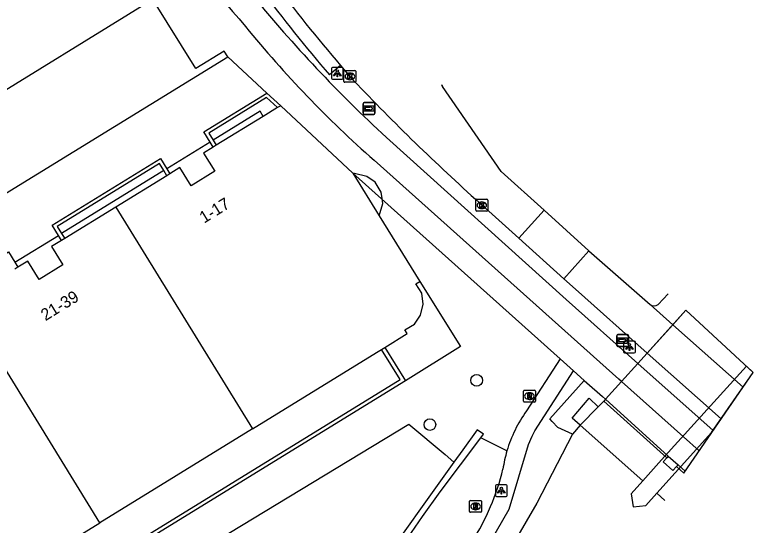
# Model space of a CAD drawing. Extents: x 160664 to 161506, y 382245 to 383288.
# Drawn here: x 161443.8 to 161505.9, y 382791.2 to 382834.1 of the extents above; entities that cross this region are included whole.
import ezdxf

# ---------------------------------------------------------------- set-up
doc = ezdxf.new("R2010")
doc.units = 0
for name, color, linetype in [('IMGEO_Berm_open', 7, 'Continuous'), ('IMGEO_Boom', 7, 'Continuous'), ('IMGEO_Dek', 7, 'Continuous'), ('IMGEO_Fietspad_gesloten', 7, 'Continuous'), ('IMGEO_Grasland_overig', 7, 'Continuous'), ('IMGEO_Groenvoorziening', 7, 'Continuous'), ('IMGEO_Haag', 7, 'Continuous'), ('IMGEO_Kolk', 7, 'Continuous'), ('IMGEO_Lichtpunt', 7, 'Continuous'), ('IMGEO_Muur', 7, 'Continuous'), ('IMGEO_Pand', 7, 'Continuous'), ('IMGEO_Pand_nummerreeks', 7, 'Continuous'), ('IMGEO_Pand_overbouw', 7, 'Continuous'), ('IMGEO_Pijler', 7, 'Continuous'), ('IMGEO_Rijbaan_lokaal_gesloten', 7, 'Continuous'), ('IMGEO_Rijbaan_lokaal_open', 7, 'Continuous'), ('IMGEO_Rioolput', 7, 'Continuous'), ('IMGEO_Stuw', 7, 'Continuous'), ('IMGEO_Verkeerseiland_gesloten', 7, 'Continuous'), ('IMGEO_Voetpad_halfverhard', 7, 'Continuous'), ('IMGEO_Voetpad_open', 7, 'Continuous'), ('IMGEO_Waterloop', 7, 'Continuous'), ('IMGEO_Wegwijzer', 7, 'Continuous')]:
    doc.layers.add(name, color=color, linetype=linetype)

msp = doc.modelspace()

# ---------------------------------------------------------------- linework, layer by layer
at = {"layer": 'IMGEO_Berm_open'}
msp.add_lwpolyline([(161471.165, 382829.87), (161470.251, 382829.074)], dxfattribs=at)
msp.add_arc((161556.487, 382903.934), 114.196, 211.69587, 220.96043, dxfattribs=at)
at = {"layer": 'IMGEO_Boom'}
for centre in [(161482.615, 382803.394), (161478.686, 382799.671)]:
    msp.add_circle(centre, 0.489, dxfattribs=at)
at = {"layer": 'IMGEO_Dek'}
msp.add_lwpolyline([(161500.029, 382795.601), (161505.863, 382804.066), (161500.209, 382809.288), (161500.209, 382809.288), (161496.961, 382805.691), (161496.176, 382804.823), (161494.795, 382803.293), (161493.457, 382801.811), (161493.311, 382801.649), (161498.591, 382796.889), (161498.306, 382796.552), (161499.095, 382795.805), (161499.425, 382796.144), (161500.029, 382795.601)], close=True, dxfattribs=at)
at = {"layer": 'IMGEO_Fietspad_gesloten'}
for points in [[(161496.176, 382804.823), (161490.146, 382810.192), (161475.03, 382823.813)], [(161494.795, 382803.293), (161494.557, 382803.506), (161473.997, 382821.895)], [(161496.176, 382804.823), (161494.795, 382803.293)], [(161502.503, 382799.191), (161496.176, 382804.823)], [(161494.795, 382803.293), (161500, 382798.638), (161501.313, 382797.464)]]:
    msp.add_lwpolyline(points, dxfattribs=at)
for centre, radius, start, end in [((161526.304, 382887.974), 83.61, 211.81634, 220.98361), ((161552.726, 382908.236), 114.734, 219.12759, 227.37602), ((161535.422, 382891.768), 93.034, 219.06402, 228.68123)]:
    msp.add_arc(centre, radius, start, end, dxfattribs=at)
at = {"layer": 'IMGEO_Grasland_overig'}
for points in [[(161464.666, 382825.575), (161464.407, 382826.011), (161460.467, 382823.586)], [(161456.306, 382821.025), (161447.73, 382815.747)], [(161477.844, 382811.705), (161481.27, 382806.236), (161476.636, 382803.355)]]:
    msp.add_lwpolyline(points, dxfattribs=at)
at = {"layer": 'IMGEO_Groenvoorziening'}
for points in [[(161406.189, 382756.415), (161409.162, 382758.244), (161452.771, 382785.073), (161476.902, 382799.706), (161479.967, 382797.156), (161480.692, 382796.508)], [(161485.158, 382797.459), (161482.963, 382798.573)]]:
    msp.add_lwpolyline(points, dxfattribs=at)
at = {"layer": 'IMGEO_Haag'}
for points in [[(161482.963, 382798.573), (161483.179, 382798.86), (161482.663, 382799.23), (161481.44, 382797.556), (161480.692, 382796.508)], [(161467.968, 382776.003), (161471.38, 382781.605), (161474.698, 382786.947), (161476.209, 382789.251), (161478.06, 382791.955), (161479.541, 382794.031), (161482.963, 382798.573)], [(161480.692, 382796.508), (161474.068, 382787.223), (161467.436, 382776.857), (161466.728, 382776.728), (161465.376, 382775.633), (161460.612, 382770.74), (161461.165, 382770.238)]]:
    msp.add_lwpolyline(points, dxfattribs=at)
at = {"layer": 'IMGEO_Kolk'}
for p, q in [((161471.461, 382828.522), (161471.461, 382829.374)), ((161471.536, 382829.448), (161472.388, 382829.448)), ((161471.949, 382829.228), (161471.974, 382829.228)), ((161472.462, 382829.374), (161472.462, 382828.522)), ((161472.388, 382828.448), (161471.536, 382828.448)), ((161471.972, 382828.668), (161471.947, 382828.668)), ((161482.549, 382817.687), (161482.549, 382818.539)), ((161482.624, 382818.613), (161483.476, 382818.613)), ((161483.55, 382818.539), (161483.55, 382817.687)), ((161483.06, 382817.833), (161483.035, 382817.833)), ((161483.037, 382818.393), (161483.062, 382818.393)), ((161483.476, 382817.613), (161482.624, 382817.613))]:
    msp.add_line(p, q, dxfattribs=at)
for points in [[(161471.461, 382828.522), (161471.461, 382829.374)], [(161471.536, 382829.448), (161472.388, 382829.448)], [(161471.782, 382829.148), (161471.905, 382829.148), (161471.905, 382828.997), (161472.035, 382829.148), (161472.199, 382829.148), (161472.053, 382828.997), (161472.206, 382828.748), (161472.054, 382828.748), (161471.969, 382828.912), (161471.905, 382828.845), (161471.905, 382828.748), (161471.782, 382828.748), (161471.782, 382829.148)], [(161472.462, 382829.374), (161472.462, 382828.522)], [(161472.388, 382828.448), (161471.536, 382828.448)], [(161482.549, 382817.687), (161482.549, 382818.539)], [(161482.624, 382818.613), (161483.476, 382818.613)], [(161483.55, 382818.539), (161483.55, 382817.687)], [(161482.87, 382818.313), (161482.993, 382818.313), (161482.993, 382818.162), (161483.123, 382818.313), (161483.287, 382818.313), (161483.141, 382818.162), (161483.294, 382817.913), (161483.142, 382817.913), (161483.057, 382818.077), (161482.993, 382818.01), (161482.993, 382817.913), (161482.87, 382817.913), (161482.87, 382818.313)], [(161483.476, 382817.613), (161482.624, 382817.613)]]:
    msp.add_lwpolyline(points, dxfattribs=at)
for centre, start, end in [((161471.538, 382829.372), 91.55205, 178.44795), ((161471.538, 382829.372), 91.55205, 178.44795), ((161472.386, 382829.372), 1.55205, 88.44795), ((161472.386, 382829.372), 1.55205, 88.44795), ((161471.538, 382828.524), 181.55205, 268.44795), ((161471.538, 382828.524), 181.55205, 268.44795), ((161472.386, 382828.524), 271.55205, 358.44795), ((161472.386, 382828.524), 271.55205, 358.44795), ((161482.626, 382818.537), 91.55205, 178.44795), ((161482.626, 382818.537), 91.55205, 178.44795), ((161483.474, 382818.537), 1.55205, 88.44795), ((161483.474, 382818.537), 1.55205, 88.44795), ((161482.626, 382817.689), 181.55205, 268.44795), ((161482.626, 382817.689), 181.55205, 268.44795), ((161483.474, 382817.689), 271.55205, 358.44795), ((161483.474, 382817.689), 271.55205, 358.44795)]:
    msp.add_arc(centre, 0.0765, start, end, dxfattribs=at)
for centre, major_axis, ratio, start_param, end_param in [((161471.948, 382828.948), (-0.387, 0.002), 0.722429, 4.712389, 7.853982), ((161471.973, 382828.948), (-0.39, 0.002), 0.717154, 1.570796, 4.712389), ((161483.036, 382818.113), (-0.387, 0.002), 0.722429, 4.712389, 7.853982), ((161483.061, 382818.113), (-0.39, 0.002), 0.717154, 1.570796, 4.712389)]:
    msp.add_ellipse(centre, major_axis=major_axis, ratio=ratio, start_param=start_param, end_param=end_param, dxfattribs=at)
at = {"layer": 'IMGEO_Lichtpunt'}
for p, q in [((161470.404, 382829.606), (161470.404, 382828.799)), ((161470.404, 382829.606), (161470.404, 382828.799)), ((161471.306, 382829.701), (161470.498, 382829.701)), ((161471.306, 382829.701), (161470.498, 382829.701)), ((161471.4, 382828.799), (161471.4, 382829.606)), ((161471.4, 382828.799), (161471.4, 382829.606)), ((161470.498, 382828.705), (161471.306, 382828.705)), ((161470.498, 382828.705), (161471.306, 382828.705)), ((161495.86, 382806.7), (161495.052, 382806.7)), ((161495.86, 382806.7), (161495.052, 382806.7)), ((161494.958, 382806.605), (161494.958, 382805.798)), ((161494.958, 382806.605), (161494.958, 382805.798)), ((161495.954, 382805.798), (161495.954, 382806.605)), ((161495.954, 382805.798), (161495.954, 382806.605)), ((161495.052, 382805.704), (161495.86, 382805.704)), ((161495.052, 382805.704), (161495.86, 382805.704)), ((161484.191, 382794.525), (161484.191, 382793.718)), ((161484.191, 382794.525), (161484.191, 382793.718)), ((161485.093, 382794.62), (161484.285, 382794.62)), ((161485.093, 382794.62), (161484.285, 382794.62)), ((161485.187, 382793.718), (161485.187, 382794.525)), ((161485.187, 382793.718), (161485.187, 382794.525)), ((161484.285, 382793.624), (161485.093, 382793.624)), ((161484.285, 382793.624), (161485.093, 382793.624))]:
    msp.add_line(p, q, dxfattribs=at)
for points in [[(161470.778, 382829.27), (161470.817, 382829.242), (161470.629, 382828.98), (161470.591, 382829.007), (161470.778, 382829.27)], [(161470.88, 382829.222), (161470.927, 382829.222), (161470.927, 382828.9), (161470.88, 382828.9), (161470.88, 382829.222)], [(161470.99, 382829.242), (161471.028, 382829.269), (161471.215, 382829.007), (161471.176, 382828.979), (161470.99, 382829.242)], [(161495.332, 382806.269), (161495.371, 382806.241), (161495.183, 382805.979), (161495.145, 382806.006), (161495.332, 382806.269)], [(161495.434, 382806.221), (161495.481, 382806.221), (161495.481, 382805.899), (161495.434, 382805.899), (161495.434, 382806.221)], [(161495.544, 382806.241), (161495.582, 382806.268), (161495.769, 382806.006), (161495.73, 382805.978), (161495.544, 382806.241)], [(161484.565, 382794.189), (161484.604, 382794.161), (161484.416, 382793.899), (161484.378, 382793.926), (161484.565, 382794.189)], [(161484.667, 382794.141), (161484.714, 382794.141), (161484.714, 382793.819), (161484.667, 382793.819), (161484.667, 382794.141)], [(161484.777, 382794.161), (161484.815, 382794.188), (161485.002, 382793.926), (161484.963, 382793.898), (161484.777, 382794.161)]]:
    msp.add_lwpolyline(points, dxfattribs=at)
for centre in [(161470.903, 382829.404), (161495.457, 382806.403), (161484.69, 382794.323)]:
    msp.add_circle(centre, 0.0994, dxfattribs=at)
for centre, start, end in [((161470.498, 382829.606), 90, 180), ((161470.498, 382829.606), 90, 180), ((161471.306, 382829.606), 0, 90), ((161471.306, 382829.606), 0, 90), ((161470.498, 382828.799), 180, 270), ((161470.498, 382828.799), 180, 270), ((161471.306, 382828.799), 270, 0), ((161471.306, 382828.799), 270, 360), ((161495.052, 382806.605), 90, 180), ((161495.052, 382806.605), 90, 180), ((161495.86, 382806.605), 0, 90), ((161495.86, 382806.605), 0, 90), ((161495.052, 382805.798), 180, 270), ((161495.052, 382805.798), 180, 270), ((161495.86, 382805.798), 270, 0), ((161495.86, 382805.798), 270, 360), ((161484.285, 382794.525), 90, 180), ((161484.285, 382794.525), 90, 180), ((161485.093, 382794.525), 0, 90), ((161485.093, 382794.525), 0, 90), ((161484.285, 382793.718), 180, 270), ((161484.285, 382793.718), 180, 270), ((161485.093, 382793.718), 270, 0), ((161485.093, 382793.718), 270, 360)]:
    msp.add_arc(centre, 0.0946, start, end, dxfattribs=at)
at = {"layer": 'IMGEO_Muur'}
for points in [[(161460.203, 382823.424), (161459.677, 382824.282), (161464.982, 382827.546)], [(161465.883, 382826.321), (161464.947, 382827.161), (161460.103, 382824.18), (161460.467, 382823.586)], [(161464.982, 382827.546), (161466.144, 382826.481)], [(161460.464, 382822.998), (161460.203, 382823.424)], [(161460.467, 382823.586), (161460.728, 382823.16)], [(161447.466, 382815.585), (161446.94, 382816.441), (161456.046, 382822.042), (161456.571, 382821.188)], [(161456.306, 382821.025), (161455.944, 382821.615), (161447.366, 382816.339), (161447.73, 382815.747)], [(161456.567, 382820.601), (161456.306, 382821.025)], [(161456.571, 382821.188), (161456.831, 382820.764)], [(161447.725, 382815.163), (161447.466, 382815.585)], [(161447.73, 382815.747), (161447.989, 382815.325)], [(161434.579, 382807.653), (161434.049, 382808.515), (161443.263, 382814.186), (161443.793, 382813.324)], [(161443.793, 382813.324), (161444.049, 382812.908)], [(161474.89, 382806.164), (161476.636, 382803.355)], [(161388.783, 382753.129), (161390.318, 382750.625), (161476.195, 382803.459), (161474.617, 382805.996)], [(161476.636, 382803.355), (161390.213, 382750.185), (161388.511, 382752.961)], [(161490.673, 382798.875), (161489.431, 382799.423), (161488.959, 382799.94), (161488.757, 382800.16), (161491.659, 382803.392)], [(161491.659, 382803.392), (161491.887, 382803.191), (161493.199, 382802.046), (161493.457, 382801.811)], [(161491.323, 382799.614), (161490.646, 382800.217), (161492.074, 382801.908), (161492.839, 382801.166)], [(161493.457, 382801.811), (161493.311, 382801.649), (161492.839, 382801.166)], [(161493.457, 382801.811), (161493.311, 382801.649), (161498.591, 382796.889)], [(161493.457, 382801.811), (161498.721, 382797.032)], [(161492.839, 382801.166), (161491.323, 382799.614)], [(161491.323, 382799.614), (161490.673, 382798.875)], [(161498.721, 382797.032), (161498.591, 382796.889)], [(161499.549, 382796.28), (161499.425, 382796.144)], [(161499.549, 382796.28), (161500.132, 382795.751)]]:
    msp.add_lwpolyline(points, dxfattribs=at)
at = {"layer": 'IMGEO_Pand'}
for points in [[(161455.402, 382835.446), (161440.09, 382825.99), (161425.287, 382849.971), (161394.286, 382830.825), (161392.2, 382834.205), (161391.899, 382834.034), (161391.641, 382834.457), (161391.935, 382834.642), (161388.103, 382840.834), (161387.809, 382840.672), (161387.548, 382841.09), (161387.832, 382841.264), (161380.859, 382852.586), (161380.561, 382852.426), (161380.303, 382852.842), (161380.588, 382853.028), (161378.773, 382855.975), (161378.129, 382865.538), (161405.343, 382882.279), (161384.524, 382916.081), (161384.366, 382916.337), (161385.135, 382916.803)], [(161465.883, 382826.321), (161464.666, 382825.575)], [(161466.144, 382826.481), (161465.883, 382826.321)], [(161466.144, 382826.481), (161472.216, 382820.812)], [(161464.666, 382825.575), (161460.728, 382823.16)], [(161460.464, 382822.998), (161459.656, 382822.502), (161460.605, 382820.972), (161458.621, 382819.749), (161457.675, 382821.283), (161456.831, 382820.764)], [(161460.728, 382823.16), (161460.464, 382822.998)], [(161456.567, 382820.601), (161452.278, 382817.963)], [(161456.831, 382820.764), (161456.567, 382820.601)], [(161472.216, 382820.812), (161474.433, 382817.224), (161477.844, 382811.705)], [(161452.278, 382817.963), (161447.989, 382815.325)], [(161452.278, 382817.963), (161463.766, 382799.312)], [(161447.989, 382815.325), (161447.725, 382815.163)], [(161447.725, 382815.163), (161446.873, 382814.639), (161447.822, 382813.109), (161445.838, 382811.886), (161444.889, 382813.425), (161444.049, 382812.908)], [(161444.049, 382812.908), (161443.785, 382812.746)], [(161474.89, 382806.164), (161476.78, 382807.328), (161476.577, 382807.634), (161477.383, 382808.122), (161477.891, 382808.886), (161478.126, 382809.803), (161478.018, 382810.726), (161477.507, 382811.513), (161477.844, 382811.705)], [(161450.937, 382791.41), (161439.442, 382810.073)], [(161474.617, 382805.996), (161474.89, 382806.164)], [(161463.766, 382799.312), (161474.202, 382805.74), (161474.617, 382805.996)], [(161463.766, 382799.312), (161450.937, 382791.41)], [(161438.101, 382783.505), (161450.937, 382791.41)]]:
    msp.add_lwpolyline(points, dxfattribs=at)
at = {"layer": 'IMGEO_Pand_overbouw'}
msp.add_lwpolyline([(161472.216, 382820.812), (161474.433, 382817.224), (161474.734, 382818.274), (161474.671, 382818.68), (161474.588, 382819.221), (161474.086, 382820.065), (161473.387, 382820.52), (161472.339, 382820.781)], close=True, dxfattribs=at)
at = {"layer": 'IMGEO_Pijler'}
msp.add_lwpolyline([(161502.369, 382798.997), (161505.863, 382804.066), (161505.31, 382804.577), (161498.144, 382796.705), (161496.572, 382794.947), (161495.592, 382793.851), (161495.763, 382792.752), (161496.822, 382792.883), (161497.746, 382793.91), (161499.288, 382795.622)], close=True, dxfattribs=at)
at = {"layer": 'IMGEO_Rijbaan_lokaal_gesloten'}
for points in [[(161471.165, 382829.87), (161471.959, 382828.949)], [(161488.276, 382817.707), (161484.669, 382820.947), (161479.743, 382828.108)], [(161482.51, 382818.637), (161486.154, 382815.355)], [(161492.054, 382814.296), (161497.188, 382809.763)], [(161489.946, 382811.939), (161490.917, 382811.064), (161496.961, 382805.691)], [(161497.188, 382809.763), (161499.103, 382808.064)], [(161499.103, 382808.064), (161496.961, 382805.691)], [(161505.008, 382802.826), (161499.103, 382808.064)], [(161496.961, 382805.691), (161503.175, 382800.166)]]:
    msp.add_lwpolyline(points, dxfattribs=at)
for centre, radius, start, end in [((161592.409, 382933.282), 159.355, 217.19712, 220.46157), ((161595.387, 382944.684), 169.202, 223.15762, 228.15505), ((161480.169, 382828.414), 0.524, 196.72835, 215.6349)]:
    msp.add_arc(centre, radius, start, end, dxfattribs=at)
at = {"layer": 'IMGEO_Rijbaan_lokaal_open'}
for points in [[(161486.154, 382815.355), (161488.276, 382817.707)], [(161488.276, 382817.707), (161492.054, 382814.296)], [(161486.154, 382815.355), (161489.946, 382811.939)], [(161489.946, 382811.939), (161492.054, 382814.296)]]:
    msp.add_lwpolyline(points, dxfattribs=at)
at = {"layer": 'IMGEO_Rioolput'}
for p, q in [((161486.547, 382801.642), (161486.547, 382802.494)), ((161486.622, 382802.568), (161487.474, 382802.568)), ((161487.035, 382802.348), (161487.06, 382802.348)), ((161487.548, 382802.494), (161487.548, 382801.642)), ((161487.058, 382801.788), (161487.033, 382801.788)), ((161487.474, 382801.568), (161486.622, 382801.568)), ((161482.025, 382792.373), (161482.025, 382793.225)), ((161482.1, 382793.299), (161482.952, 382793.299)), ((161482.513, 382793.079), (161482.538, 382793.079)), ((161483.026, 382793.225), (161483.026, 382792.373)), ((161482.536, 382792.519), (161482.511, 382792.519)), ((161482.952, 382792.299), (161482.1, 382792.299))]:
    msp.add_line(p, q, dxfattribs=at)
for points in [[(161486.547, 382801.642), (161486.547, 382802.494)], [(161486.622, 382802.568), (161487.474, 382802.568)], [(161487.548, 382802.494), (161487.548, 382801.642)], [(161487.136, 382802.266), (161486.884, 382802.268), (161486.884, 382801.868)], [(161486.884, 382801.868), (161487.008, 382801.868), (161487.008, 382802.03), (161487.019, 382802.03)], [(161487.062, 382802.187), (161487.008, 382802.187), (161487.008, 382802.106)], [(161487.008, 382802.106), (161487.06, 382802.106)], [(161487.066, 382802.001), (161487.137, 382801.868), (161487.277, 382801.868), (161487.212, 382801.994)], [(161487.474, 382801.568), (161486.622, 382801.568)], [(161482.025, 382792.373), (161482.025, 382793.225)], [(161482.1, 382793.299), (161482.952, 382793.299)], [(161482.614, 382792.997), (161482.362, 382792.999), (161482.362, 382792.599)], [(161483.026, 382793.225), (161483.026, 382792.373)], [(161482.362, 382792.599), (161482.486, 382792.599), (161482.486, 382792.761), (161482.497, 382792.761)], [(161482.54, 382792.918), (161482.486, 382792.918), (161482.486, 382792.837)], [(161482.486, 382792.837), (161482.538, 382792.837)], [(161482.544, 382792.732), (161482.615, 382792.599), (161482.755, 382792.599), (161482.69, 382792.725)], [(161482.952, 382792.299), (161482.1, 382792.299)]]:
    msp.add_lwpolyline(points, dxfattribs=at)
for centre, radius, start, end in [((161486.624, 382802.492), 0.0765, 91.55205, 178.44795), ((161486.624, 382802.492), 0.0765, 91.55205, 178.44795), ((161487.472, 382802.492), 0.0765, 1.55205, 88.44795), ((161487.472, 382802.492), 0.0765, 1.55205, 88.44795), ((161487.018, 382801.977), 0.0533, 26.02933, 88.69889), ((161487.044, 382802.295), 0.19, 274.7715, 282.96867), ((161487.068, 382802.091), 0.0964, 77.00612, 93.18647), ((161487.082, 382802.148), 0.0378, 276.66336, 79.67722), ((161487.135, 382802.156), 0.109, 350.36119, 89.41601), ((161487.133, 382802.156), 0.112, 277.58423, 350.98172), ((161487.117, 382801.941), 0.108, 29.51342, 73.79051), ((161486.624, 382801.644), 0.0765, 181.55205, 268.44795), ((161486.624, 382801.644), 0.0765, 181.55205, 268.44795), ((161487.472, 382801.644), 0.0765, 271.55205, 358.44795), ((161487.472, 382801.644), 0.0765, 271.55205, 358.44795), ((161482.102, 382793.223), 0.0765, 91.55205, 178.44795), ((161482.102, 382793.223), 0.0765, 91.55205, 178.44795), ((161482.613, 382792.887), 0.109, 350.36119, 89.41601), ((161482.95, 382793.223), 0.0765, 1.55205, 88.44795), ((161482.95, 382793.223), 0.0765, 1.55205, 88.44795), ((161482.102, 382792.375), 0.0765, 181.55205, 268.44795), ((161482.102, 382792.375), 0.0765, 181.55205, 268.44795), ((161482.496, 382792.708), 0.0533, 26.02933, 88.69889), ((161482.522, 382793.026), 0.19, 274.7715, 282.96867), ((161482.546, 382792.822), 0.0964, 77.00612, 93.18647), ((161482.56, 382792.879), 0.0378, 276.66336, 79.67722), ((161482.611, 382792.887), 0.112, 277.58423, 350.98172), ((161482.595, 382792.672), 0.108, 29.51342, 73.79051), ((161482.95, 382792.375), 0.0765, 271.55205, 358.44795), ((161482.95, 382792.375), 0.0765, 271.55205, 358.44795)]:
    msp.add_arc(centre, radius, start, end, dxfattribs=at)
for centre, major_axis, ratio, start_param, end_param in [((161487.034, 382802.068), (-0.387, 0.002), 0.722429, 4.712389, 7.853982), ((161487.059, 382802.068), (-0.39, 0.002), 0.717154, 1.570796, 4.712389), ((161482.512, 382792.799), (-0.387, 0.002), 0.722429, 4.712389, 7.853982), ((161482.537, 382792.799), (-0.39, 0.002), 0.717154, 1.570796, 4.712389)]:
    msp.add_ellipse(centre, major_axis=major_axis, ratio=ratio, start_param=start_param, end_param=end_param, dxfattribs=at)
at = {"layer": 'IMGEO_Stuw'}
for points in [[(161496.572, 382794.947), (161491.323, 382799.614)], [(161498.435, 382793.288), (161497.746, 382793.91)]]:
    msp.add_lwpolyline(points, dxfattribs=at)
at = {"layer": 'IMGEO_Verkeerseiland_gesloten'}
msp.add_lwpolyline([(161498.704, 382810.679), (161497.872, 382809.777)], dxfattribs=at)
msp.add_arc((161497.521, 382810.207), 0.555, 233.10319, 309.24192, dxfattribs=at)
at = {"layer": 'IMGEO_Voetpad_halfverhard'}
for points in [[(161489.644, 382805.196), (161486.808, 382800.822)], [(161470.923, 382767.409), (161471.449, 382768.45), (161485.344, 382792.552), (161486.982, 382797.992), (161487.291, 382798.689), (161487.508, 382799.156), (161490.763, 382804.194)]]:
    msp.add_lwpolyline(points, dxfattribs=at)
for centre, radius, start, end in [((161495.855, 382794.297), 11.155, 144.19993, 163.53185), ((161495.834, 382794.307), 11.131, 163.55106, 171.55923), ((161465.317, 382800.601), 20.055, 327.49992, 346.565)]:
    msp.add_arc(centre, radius, start, end, dxfattribs=at)
at = {"layer": 'IMGEO_Voetpad_open'}
for points in [[(161461.698, 382830.581), (161461.397, 382831.066), (161459, 382829.604), (161455.402, 382835.446)], [(161410.249, 382798.968), (161461.698, 382830.581)], [(161461.698, 382830.581), (161464.982, 382827.546)], [(161460.203, 382823.424), (161456.571, 382821.188)], [(161489.644, 382805.196), (161472.216, 382820.812)], [(161443.793, 382813.324), (161447.466, 382815.585)], [(161490.763, 382804.194), (161489.644, 382805.196)], [(161490.763, 382804.194), (161491.659, 382803.392)], [(161494.795, 382803.293), (161493.457, 382801.811)], [(161498.591, 382796.889), (161498.306, 382796.552), (161499.095, 382795.805), (161499.425, 382796.144)], [(161498.721, 382797.032), (161499.549, 382796.28)]]:
    msp.add_lwpolyline(points, dxfattribs=at)
at = {"layer": 'IMGEO_Waterloop'}
for points in [[(161500.209, 382809.288), (161500.209, 382809.288), (161499.103, 382808.064)], [(161496.961, 382805.691), (161496.176, 382804.823)], [(161490.673, 382798.875), (161487.679, 382793.068), (161471.829, 382765.848), (161471.412, 382765.267), (161470.199, 382765.758)]]:
    msp.add_lwpolyline(points, dxfattribs=at)
at = {"layer": 'IMGEO_Wegwijzer'}
for p, q in [((161473.07, 382825.853), (161473.07, 382826.653)), ((161473.07, 382826.653), (161473.07, 382825.853)), ((161473.17, 382826.753), (161473.96, 382826.753)), ((161473.96, 382826.753), (161473.17, 382826.753)), ((161474.06, 382826.653), (161474.06, 382825.853)), ((161474.06, 382825.853), (161474.06, 382826.653)), ((161473.96, 382825.753), (161473.17, 382825.753)), ((161473.17, 382825.753), (161473.96, 382825.753)), ((161494.386, 382806.336), (161494.386, 382807.136)), ((161494.386, 382807.136), (161494.386, 382806.336)), ((161494.486, 382807.236), (161495.276, 382807.236)), ((161495.276, 382807.236), (161494.486, 382807.236)), ((161495.376, 382807.136), (161495.376, 382806.336)), ((161495.376, 382806.336), (161495.376, 382807.136)), ((161495.276, 382806.236), (161494.486, 382806.236)), ((161494.486, 382806.236), (161495.276, 382806.236))]:
    msp.add_line(p, q, dxfattribs=at)
for points in [[(161473.171, 382826.485), (161473.959, 382826.485), (161473.959, 382826.021), (161473.171, 382826.021), (161473.171, 382826.485)], [(161473.236, 382826.337), (161473.236, 382826.253), (161473.236, 382826.169), (161473.647, 382826.169), (161473.647, 382826.086), (161473.894, 382826.253), (161473.647, 382826.42), (161473.647, 382826.337), (161473.236, 382826.337)], [(161494.487, 382806.968), (161495.275, 382806.968), (161495.275, 382806.504), (161494.487, 382806.504), (161494.487, 382806.968)], [(161494.552, 382806.82), (161494.552, 382806.736), (161494.552, 382806.652), (161494.963, 382806.652), (161494.963, 382806.569), (161495.21, 382806.736), (161494.963, 382806.903), (161494.963, 382806.82), (161494.552, 382806.82)]]:
    msp.add_lwpolyline(points, dxfattribs=at)
for centre, start, end in [((161473.17, 382826.653), 90, 180), ((161473.17, 382826.653), 90, 180), ((161473.96, 382826.653), 0, 90), ((161473.96, 382826.653), 360, 90), ((161473.17, 382825.853), 180, 270), ((161473.17, 382825.853), 180, 270), ((161473.96, 382825.853), 270, 0), ((161473.96, 382825.853), 270, 0), ((161494.486, 382807.136), 90, 180), ((161494.486, 382807.136), 90, 180), ((161495.276, 382807.136), 0, 90), ((161495.276, 382807.136), 360, 90), ((161494.486, 382806.336), 180, 270), ((161494.486, 382806.336), 180, 270), ((161495.276, 382806.336), 270, 0), ((161495.276, 382806.336), 270, 0)]:
    msp.add_arc(centre, 0.1, start, end, dxfattribs=at)

# ---------------------------------------------------------------- texts
at = {"layer": 'IMGEO_Pand_nummerreeks'}
for s, p in [('1-17', (161459.7, 382816.561)), ('21-39', (161446.369, 382808.36))]:
    msp.add_text(s, height=1, rotation=31.65099, dxfattribs=at).set_placement(p)

doc.saveas('drawing.dxf')
